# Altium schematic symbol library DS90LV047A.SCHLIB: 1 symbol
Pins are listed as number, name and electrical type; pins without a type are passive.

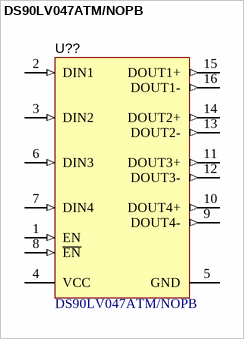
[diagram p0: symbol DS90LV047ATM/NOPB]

## DS90LV047ATM/NOPB
designator U??
3V LVDS Quad CMOS Differential Line Driver, 16-pin Narrow SOIC, Pb-Free; Manufacturer: Texas Instruments; PackageTopMarking: NS2ZXYTTE#*DS90LV047A*TM; PowerWise: N; CompType: Interface IC
footprint M16A_N (SOIC, 16-Leads, Body 9.9x3.9mm, Pitch 1.27mm, IPC Medium Density)
footprint M16A_L (SOIC, 16-Leads, Body 9.9x3.9mm, Pitch 1.27mm, IPC High Density)
footprint M16A_M (SOIC, 16-Leads, Body 9.9x3.9mm, Pitch 1.27mm, IPC Low Density)
pins: 1 EN (in), 2 DIN1 (in), 3 DIN2 (in), 4 VCC (power), 5 GND (power), 6 DIN3 (in), 7 DIN4 (in), 8 ~{EN} (in), 9 DOUT4- (out), 10 DOUT4+ (out), 11 DOUT3+ (out), 12 DOUT3- (out), 13 DOUT2- (out), 14 DOUT2+ (out), 15 DOUT1+ (out), 16 DOUT1- (out)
